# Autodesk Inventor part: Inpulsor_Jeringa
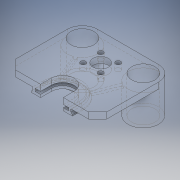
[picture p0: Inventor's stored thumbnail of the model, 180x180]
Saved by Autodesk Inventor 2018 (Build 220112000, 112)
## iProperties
Part Number: Inpulsor_Jeringa
Material: Genérico
Document SubType Name: Modeling
Designer: ULISES
Density: 1 g/cm^3
Appearance: Valor por defecto
Author: ULISES
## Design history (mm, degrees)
sketch "Boceto1"
  geometry: L1 (0, 0)-(60, 0); L2 (60, 0)-(60, 50); L3 (60, 50)-(0, 50); L4 (0, 50)-(0, 0); C1 r 7.6 at (10, 40); C2 r 7.6 at (50, 40); C3 r 5.05 at (30, 32); C4 r 1.65 at (35.75, 37.75); C5 r 1.65 at (24.25, 37.75); C6 r 1.65 at (24.25, 26.25); C7 r 1.65 at (35.75, 26.25)
  constraints: 8 end point, 7 centre point, 2 parallel, 1 horizontal, 1 horizontal alignment, 1 perpendicular, 9 other
  dimensions: "d0" = 40 distance of C2.centre C1.centre; "d1" = 10 distance from line of L2 C2.centre (= 0.5 x d2 - 0.5 x d0); "d2" = 60 distance of L2.end L3.end; "d3" = 8 vertical distance of C2.centre C3.centre; "d4" = 50 distance of L1.end L2.end; "d5" = 20 horizontal distance of C2.centre C3.centre (= 0.5 x d0); "d6" = 10 distance from line of L3 C2.centre (= d1); "d7" = 15.2 diameter of C2; "d8" = 15.2 diameter of C1; "d9" = 10.1 diameter of C3; "d15" = 5.75 horizontal distance of C3.centre C4.centre; "d16" = 5.75 horizontal distance of C4.centre C3.centre (= d15); "d17" = 3.3 diameter of C4; "d20" = 360 deg dimension on C3.centre C4.centre (derived)
extrude "Extrusión1" new body sketch "Boceto1" distance "d10" = 4; taper "d11" = 0 deg
sketch "Boceto2"
  geometry: L1 (0, 50)-(0, 0) reference; L2 (-60, 0)-(-60, 50) reference; C1 r 7.6 at (-10, 40) reference; C2 r 7.6 at (-50, 40) reference; C3 r 10 at (-10, 40); C4 r 10 at (-50, 40)
  constraints: 2 centre point, 2 tangent
extrude "Extrusión2" join sketch "Boceto2" distance "d12" = 20; taper "d13" = 0 deg
fillet "Empalme1" dims "d14" = 10
sketch "Boceto4" dims "d23" = 15
  geometry: L1 (-50, 50)-(-10, 50) reference; L2 (-60, 0)-(-60, 40) reference; L3 (0, 0)-(-60, 0) reference; L4 (0, 40)-(0, 0) reference; L5 (-37.5, 7)-(-22.5, 7); L6 (-22.5, 7)-(-22.5, -9); L7 (-22.5, -9)-(-37.5, -9); L8 (-37.5, -9)-(-37.5, 7); C1 r 5.05 at (-30, 32) reference; C2 r 5.05 at (-30, 32) reference; C3 r 1.65 at (-35.75, 26.25) reference; C4 r 1.65 at (-24.25, 26.25) reference; C5 r 1.65 at (-24.25, 37.75) reference; C6 r 1.65 at (-35.75, 37.75) reference; A1 r 10 centre (-10, 40) between (-10, 50) and (0, 40) reference; A2 r 10 centre (-50, 40) between (-60, 40) and (-50, 50) reference; 2 further points
  constraints: 8 end point, 2 parallel, 2 vertical, 1 horizontal, 1 horizontal alignment, 1 perpendicular, 1 vertical alignment, 2 other
  dimensions: "d22" = 25 distance of point (-30, 7) C1.centre; "d24" = 16 distance of L5.end L6.end
extrude "Extrusión3" cut sketch "Boceto4" distance "d25" = 10; taper "d26" = 0 deg
sketch "Boceto7"
  geometry: L1 (-37.5, 0)-(-37.5, 7) reference; L2 (-22.5, 7)-(-22.5, 0) reference; L3 (-41, 0)-(-41, 7); L4 (-19, 7)-(-19, 0); L5 (-42.5, 0)-(-42.5, 7); L6 (-17.5, 7)-(-17.5, 0); L7 (0, 0)-(-22.5, 0) reference; L8 (-42.5, 0)-(-41, 0); L9 (-19, 0)-(-17.5, 0); A1 r 7.5 centre (-30, 7) between (-22.5, 7) and (-37.5, 7) reference; A2 r 11 centre (-30, 7) between (-19, 7) and (-41, 7); A3 r 12.5 centre (-30, 7) between (-17.5, 7) and (-42.5, 7)
  constraints: 14 end point, 4 point on circle, 2 centre point, 2 collinear, 4 other
  dimensions: "d30" = 3.5 radial gap between concentric circles of A1 A2; "d31" = 1.5 radial gap between concentric circles of A2 A3; "d39" = 7.5 radius of A1 (derived); "d40" = 11 radius of A2 (derived)
extrude "Extrusión5" join sketch "Boceto7" distance "d32" = 1.8; taper "d33" = 0 deg
sketch "Boceto8"
  geometry: L1 (-41, 0)-(-41, 7) reference; L2 (-19, 7)-(-19, 0) reference; L3 (-19, 0)-(-17.5, 0) reference; L4 (-17.5, 0)-(-17.5, 7) reference; L5 (-42.5, 7)-(-42.5, 0) reference; L6 (-42.5, 0)-(-41, 0) reference; L7 (-19, 0)-(-19, 7) reference; L8 (-41, 7)-(-41, 0) reference; L9 (-37.5, 0)-(-41, 0) reference; L10 (-37.5, 0)-(-37.5, 7) reference; L11 (-22.5, 7)-(-22.5, 0) reference; L12 (-19, 0)-(-22.5, 0) reference; L13 (-16.5, 7)-(-16.5, 0); L14 (-43.5, 0)-(-43.5, 7); L15 (-42.5, 0)-(-60, 0) reference; L16 (-19, 0)-(-22.5, 0) reference; L17 (-17.5, 0)-(-16.5, 0); L18 (-43.5, 0)-(-42.5, 0); L19 (-41, 0)-(-40.356, 0); A1 r 11 centre (-30, 7) between (-19, 7) and (-41, 7) reference; A2 r 12.5 centre (-30, 7) between (-17.5, 7) and (-42.5, 7) reference; A3 r 11 centre (-30, 7) between (-19, 7) and (-41, 7) reference; A4 r 7.5 centre (-30, 7) between (-22.5, 7) and (-37.5, 7) reference; A5 r 13.5 centre (-30, 7) between (-16.5, 7) and (-43.5, 7); 1 further point
  constraints: 14 end point, 3 collinear, 3 point on circle, 1 centre point, 1 point on line
  dimensions: "d41" = 1 radial gap between concentric circles of A2 A5
extrude "Extrusión6" join sketch "Boceto8" distance "d34" = 1.8; taper "d35" = 0 deg
chamfer "Chaflán1" distance "d36" = 1; stored, may be unused: second distance "d37" = 2, angle "d38" = 45 deg
chamfer "Chaflán2" distance "d42" = 6; stored, may be unused: second distance "d43" = 2, angle "d44" = 45 deg
sketch "Boceto9"
  geometry: L1 (-15.282, 31.509)-(-21.486, 16.152); L2 (-13.481, 30.626)-(-19.998, 14.497); L3 (-6, 0)-(-17.5, 0) reference; L4 (-30, 0)-(-30, 7); L5 (-44.718, 31.509)-(-38.514, 16.152); L6 (-46.519, 30.626)-(-40.002, 14.497); A1 r 10 centre (-10, 40) between (-15.282, 31.509) and (-13.481, 30.626) reference; A2 r 12.5 centre (-30, 7) between (-17.5, 7) and (-42.5, 7) reference; A3 r 10 centre (-50, 40) between (-60, 40) and (-50, 50) reference; A4 r 10 centre (-50, 40) between (-44.718, 31.509) and (-46.519, 30.626); A5 r 12.5 centre (-30, 7) between (-17.5, 7) and (-42.5, 7); 1 further point
  constraints: 10 end point, 10 point on circle, 7 symmetric about line, 2 centre point, 1 parallel, 1 vertical, 2 other
  dimensions: "d45" = 2 distance between parallel lines of L1 L2; "d46" = 68 deg angle of L1 L3
extrude "Extrusión7" join sketch "Boceto9" distance "d47" = 1.5; taper "d48" = 0 deg
node "Sólido1"
node "Contorno proyectado1"
node "Contorno proyectado3"
node "Contorno proyectado4"
